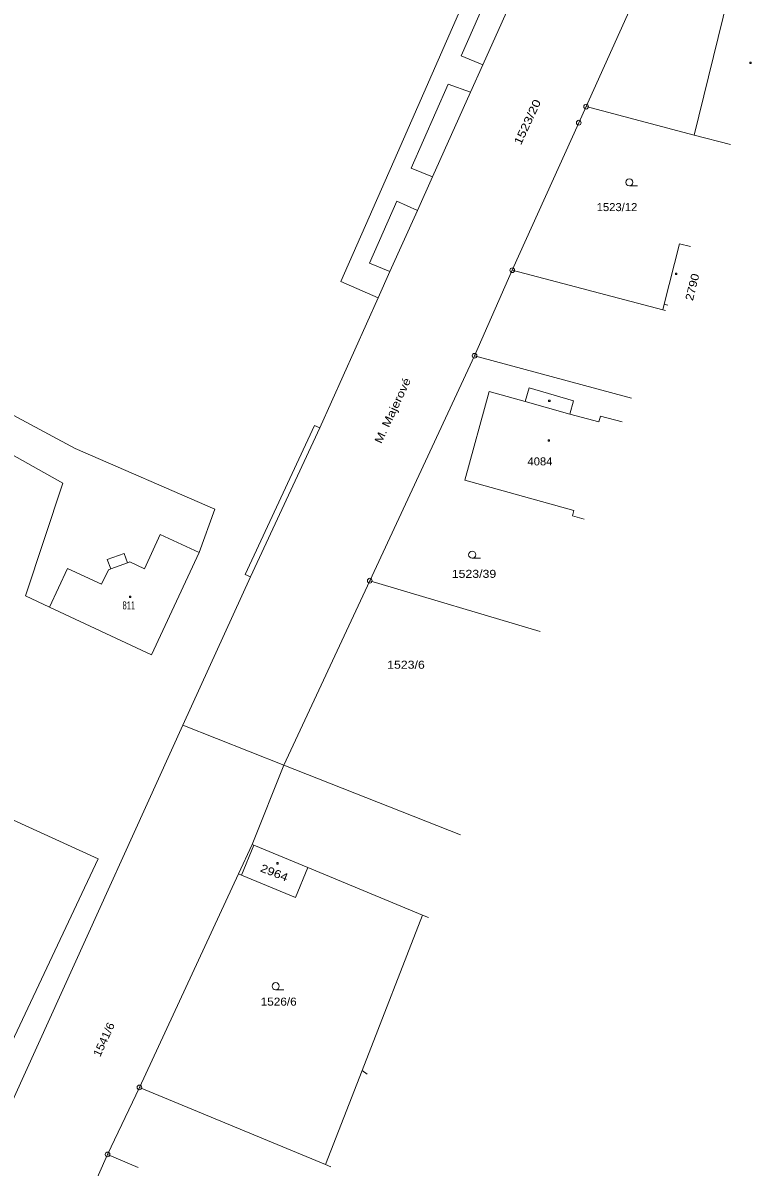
# Model space of a CAD drawing. Extents: x -630464 to -630140, y -1004543 to -1004208.
# Drawn here: x -630237.7 to -630160.4, y -1004467.8 to -1004346.3 of the extents above; entities that cross this region are included whole.
import ezdxf

# ---------------------------------------------------------------- set-up
doc = ezdxf.new("R2010")
doc.units = 0
doc.header["$LTSCALE"] = 0.34
for name, color, linetype, lineweight in [('1', 7, 'Continuous', 13), ('2', 7, 'Continuous', 13), ('23', 7, 'Continuous', 13), ('25', 7, 'Continuous', 13), ('28', 7, 'Continuous', 13)]:
    doc.layers.add(name, color=color, linetype=linetype, lineweight=lineweight)
for name, color, linetype in [('14', 7, 'Continuous'), ('15', 7, 'Continuous'), ('38', 7, 'Continuous')]:
    doc.layers.add(name, color=color, linetype=linetype)

msp = doc.modelspace()

# ---------------------------------------------------------------- linework, layer by layer
at = {"layer": '1'}
for p, q in [((-630166.4, -1004358.22), (-630162.558, -1004359.229)), ((-630167.97, -1004369.77), (-630166.795, -1004370.066)), ((-630169.74, -1004376.78), (-630169.45, -1004376.857)), ((-630200.86, -1004405.54), (-630189.74, -1004381.66)), ((-630189.74, -1004381.66), (-630173.087, -1004386.159)), ((-630179.61, -1004387.86), (-630179.22, -1004386.43)), ((-630179.61, -1004387.86), (-630176.55, -1004388.69)), ((-630176.55, -1004388.69), (-630176.38, -1004388.07)), ((-630176.38, -1004388.07), (-630174.077, -1004388.69)), ((-630241.9, -1004390.45), (-630233.45, -1004395.18)), ((-630232.16, -1004391.49), (-630217.31, -1004397.96)), ((-630190.78, -1004394.86), (-630179.2, -1004398.1)), ((-630237.43, -1004407.16), (-630233.45, -1004395.18)), ((-630179.35, -1004398.64), (-630179.2, -1004398.1)), ((-630179.35, -1004398.64), (-630178.105, -1004398.992)), ((-630228.74, -1004403.29), (-630226.95, -1004402.64)), ((-630228.74, -1004403.29), (-630228.37, -1004404.29)), ((-630228.62, -1004404.38), (-630228.37, -1004404.29)), ((-630209.99, -1004425.12), (-630200.86, -1004405.54)), ((-630200.86, -1004405.54), (-630182.771, -1004410.926)), ((-630237.43, -1004407.16), (-630234.88, -1004408.35)), ((-630234.88, -1004408.35), (-630224.04, -1004413.4)), ((-630213.35, -1004433.54), (-630209.99, -1004425.12)), ((-630209.99, -1004425.12), (-630191.217, -1004432.528)), ((-630201.67, -1004457.54), (-630195.25, -1004441.04)), ((-630195.25, -1004441.04), (-630194.643, -1004441.291)), ((-630205.56, -1004467.54), (-630201.67, -1004457.54)), ((-630201.67, -1004457.54), (-630201.149, -1004457.933)), ((-630228.7, -1004466.46), (-630225.32, -1004459.34)), ((-630225.32, -1004459.34), (-630205.56, -1004467.54)), ((-630233.63, -1004477.39), (-630228.7, -1004466.46)), ((-630228.7, -1004466.46), (-630225.45, -1004467.84)), ((-630205.56, -1004467.54), (-630204.997, -1004467.774))]:
    msp.add_line(p, q, dxfattribs=at)
for points in [[(-630199.97, -1004375.5), (-630203.94, -1004373.79), (-630197.92, -1004360.13), (-630189.91, -1004341.84), (-630181.84, -1004323.63), (-630180.31, -1004323.98), (-630179.33, -1004319.62), (-630180.1, -1004316.43)], [(-630206.18, -1004389.32), (-630199.97, -1004375.5), (-630198.73, -1004372.73), (-630195.8, -1004366.22), (-630194.2, -1004362.66), (-630190.16, -1004353.66), (-630188.86, -1004350.78), (-630183.01, -1004337.75), (-630181.83, -1004335.12), (-630177.5, -1004325.49), (-630176.7, -1004323.71)], [(-630177.89, -1004355.21), (-630168.8, -1004335), (-630166.88, -1004330.85)], [(-630185.73, -1004372.58), (-630178.67, -1004356.91), (-630177.89, -1004355.21), (-630166.4, -1004358.22)], [(-630169.74, -1004376.78), (-630169.59, -1004376.18), (-630167.97, -1004369.77)], [(-630189.74, -1004381.66), (-630185.73, -1004372.58), (-630169.74, -1004376.78)], [(-630245.38, -1004376.09), (-630240.68, -1004386.95), (-630232.16, -1004391.49)], [(-630190.78, -1004394.86), (-630188.18, -1004385.44), (-630184.36, -1004386.51), (-630183.95, -1004385.08), (-630179.22, -1004386.43)], [(-630220.7, -1004420.89), (-630213.54, -1004405.13), (-630206.18, -1004389.32)], [(-630224.04, -1004413.4), (-630218.99, -1004402.56), (-630217.31, -1004397.96)], [(-630226.95, -1004402.64), (-630226.59, -1004403.64), (-630226.34, -1004403.55), (-630224.79, -1004404.27), (-630223.11, -1004400.64), (-630218.99, -1004402.56)], [(-630234.88, -1004408.35), (-630232.96, -1004404.24), (-630229.34, -1004405.92), (-630228.62, -1004404.38)], [(-630254.2, -1004486.47), (-630251.14, -1004485.59), (-630248.99, -1004483.18), (-630220.7, -1004420.89), (-630209.99, -1004425.12)], [(-630214.8, -1004436.67), (-630213.35, -1004433.54), (-630213.17, -1004433.61), (-630207.44, -1004435.99)], [(-630225.32, -1004459.34), (-630214.8, -1004436.67), (-630214.49, -1004436.8), (-630208.76, -1004439.18), (-630207.44, -1004435.99), (-630195.25, -1004441.04)]]:
    msp.add_lwpolyline(points, dxfattribs=at)
at = {"layer": '2'}
for p, q in [((-630166.4, -1004358.22), (-630162.52, -1004342.29)), ((-630169.59, -1004376.18), (-630169.221, -1004376.271)), ((-630184.36, -1004386.51), (-630179.61, -1004387.86)), ((-630228.37, -1004404.29), (-630226.59, -1004403.64)), ((-630214.09, -1004404.87), (-630213.54, -1004405.13)), ((-630282.83, -1004410.76), (-630229.71, -1004435.08)), ((-630214.49, -1004436.8), (-630213.17, -1004433.61)), ((-630240.77, -1004458.53), (-630229.71, -1004435.08))]:
    msp.add_line(p, q, dxfattribs=at)
for points in [[(-630188.86, -1004350.78), (-630191.17, -1004349.81), (-630185.4, -1004336.73), (-630183.01, -1004337.75)], [(-630194.2, -1004362.66), (-630196.46, -1004361.74), (-630192.53, -1004352.83), (-630190.16, -1004353.66)], [(-630198.73, -1004372.73), (-630200.88, -1004371.81), (-630197.99, -1004365.25), (-630195.8, -1004366.22)], [(-630214.09, -1004404.87), (-630206.73, -1004389.06), (-630206.18, -1004389.32)]]:
    msp.add_lwpolyline(points, dxfattribs=at)
at = {"layer": '23'}
for p, q in [((-630173.3, -1004363.62), (-630172.425, -1004363.62)), ((-630189.99, -1004403.16), (-630189.115, -1004403.16)), ((-630210.86, -1004448.97), (-630209.985, -1004448.97))]:
    msp.add_line(p, q, dxfattribs=at)
for centre in [(-630173.3, -1004363.245), (-630189.99, -1004402.785), (-630210.86, -1004448.595)]:
    msp.add_circle(centre, 0.375, dxfattribs=at)
at = {"layer": '25'}
for points in [[(-630160.52, -1004350.47), (-630160.37, -1004350.47), (-630160.37, -1004350.62), (-630160.52, -1004350.62)], [(-630168.41, -1004372.89), (-630168.26, -1004372.89), (-630168.26, -1004373.04), (-630168.41, -1004373.04)], [(-630181.87, -1004386.38), (-630181.72, -1004386.38), (-630181.72, -1004386.53), (-630181.87, -1004386.53)], [(-630181.93, -1004390.59), (-630181.78, -1004390.59), (-630181.78, -1004390.74), (-630181.93, -1004390.74)], [(-630226.39, -1004407.17), (-630226.24, -1004407.17), (-630226.24, -1004407.32), (-630226.39, -1004407.32)], [(-630210.75, -1004435.48), (-630210.6, -1004435.48), (-630210.6, -1004435.63), (-630210.75, -1004435.63)]]:
    msp.add_lwpolyline(points, close=True, dxfattribs=at)
at = {"layer": '28'}
for centre, radius in [((-630177.89, -1004355.21), 0.25), ((-630177.89, -1004355.21), 0.005), ((-630178.67, -1004356.91), 0.25), ((-630178.67, -1004356.91), 0.005), ((-630185.73, -1004372.58), 0.25), ((-630185.73, -1004372.58), 0.005), ((-630189.74, -1004381.66), 0.25), ((-630189.74, -1004381.66), 0.005), ((-630200.86, -1004405.54), 0.25), ((-630200.86, -1004405.54), 0.005), ((-630225.32, -1004459.34), 0.25), ((-630225.32, -1004459.34), 0.005), ((-630228.7, -1004466.46), 0.25), ((-630228.7, -1004466.46), 0.005)]:
    msp.add_circle(centre, radius, dxfattribs=at)

# ---------------------------------------------------------------- texts
at = {"layer": '14'}
for s, rotation, width, p in [('1523/20', 65.111, 1.25, (-630184.82, -1004359.35)), ('1541/6', 65.459, 1.1, (-630229.5, -1004456.17))]:
    msp.add_text(s, height=0.85, rotation=rotation, dxfattribs=dict(at, width=width)).set_placement(p)
for s, width, p in [('1523/12', 1.05, (-630176.77, -1004366.3)), ('1523/39', 1.15, (-630192.16, -1004405.24)), ('1523/6', 1.15, (-630199.02, -1004414.89)), ('1526/6', 1.1, (-630212.45, -1004450.66))]:
    msp.add_text(s, height=0.85, dxfattribs=dict(at, width=width)).set_placement(p)
at = {"layer": '15'}
for s, rotation, width, p in [('2790', 76.074, 1.15, (-630166.56, -1004375.88)), ('2964', 338.63, 1.2, (-630212.57, -1004436.39))]:
    msp.add_text(s, height=0.85, rotation=rotation, dxfattribs=dict(at, width=width)).set_placement(p)
for s, width, p in [('4084', 1.05, (-630184.12, -1004393.3)), ('811', 0.65, (-630227.12, -1004408.59))]:
    msp.add_text(s, height=0.85, dxfattribs=dict(at, width=width)).set_placement(p)
at = {"layer": '38', "width": 1.2}
msp.add_text('M. Majerové', height=0.85, rotation=65.025, dxfattribs=at).set_placement((-630199.64, -1004391.06))

doc.saveas('drawing.dxf')
